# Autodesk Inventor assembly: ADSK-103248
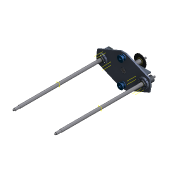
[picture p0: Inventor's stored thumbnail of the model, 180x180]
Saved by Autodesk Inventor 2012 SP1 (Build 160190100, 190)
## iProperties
Shininess: 0.0
Created: 2000-12
Part Number: ADSK-103248
Document SubType Name: Assembly
Designer: gao
Stock Number: ADSK-103248
Density: 0.0
Volumn: 0.0
Area: 0.0
PropertySet Name: Model Information
Control State: 0
Master: False
Checked Out: False
Author: gao
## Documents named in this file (15)
- D:\AOTC\Autodesk Inventor 2012 Essential for New Users\Autodesk Inventor 2012 Essentials - Project Files\Learning\Workspace\Sub-Assemblies\ADSK-103248.iam
- D:\AOTC\Autodesk Inventor 2012 Essential for New Users\Autodesk Inventor 2012 Essentials - Project Files\Learning\Workspace\Parts\ADSK-104071.ipt
- D:\AOTC\Autodesk Inventor 2012 Essential for New Users\Autodesk Inventor 2012 Essentials - Project Files\Learning\Workspace\Libraries\Content Center Files\en-US\4746AD94-7A15-4D0E-79EA-365386ECB28E.ipt
- D:\AOTC\Autodesk Inventor 2012 Essential for New Users\Autodesk Inventor 2012 Essentials - Project Files\Learning\Workspace\Sub-Assemblies\ADSK-103235.iam
- D:\AOTC\Autodesk Inventor 2012 Essential for New Users\Autodesk Inventor 2012 Essentials - Project Files\Learning\Workspace\Parts\ADSK-103456.ipt
- D:\AOTC\Autodesk Inventor 2012 Essential for New Users\Autodesk Inventor 2012 Essentials - Project Files\Learning\Workspace\Parts\ADSK-103406.ipt
- D:\AOTC\Autodesk Inventor 2012 Essential for New Users\Autodesk Inventor 2012 Essentials - Project Files\Learning\Workspace\Sub-Assemblies\ADSK-103223.iam
- D:\AOTC\Autodesk Inventor 2012 Essential for New Users\Autodesk Inventor 2012 Essentials - Project Files\Learning\Workspace\Parts\ADSK-103915.ipt
- D:\AOTC\Autodesk Inventor 2012 Essential for New Users\Autodesk Inventor 2012 Essentials - Project Files\Learning\Workspace\Parts\ADSK-103391.ipt
- D:\AOTC\Autodesk Inventor 2012 Essential for New Users\Autodesk Inventor 2012 Essentials - Project Files\Learning\Workspace\Parts\ADSK-104022.ipt
- D:\AOTC\Autodesk Inventor 2012 Essential for New Users\Autodesk Inventor 2012 Essentials - Project Files\Learning\Workspace\Parts\ADSK-103457.ipt
- D:\AOTC\Autodesk Inventor 2012 Essential for New Users\Autodesk Inventor 2012 Essentials - Project Files\Learning\Workspace\Parts\45665CD9-1C60-DBCA-D3BB-54EB80893890.ipt
- D:\AOTC\Autodesk Inventor 2012 Essential for New Users\Autodesk Inventor 2012 Essentials - Project Files\Learning\Workspace\Parts\F3808AAD-BDC4-3728-F238-65C25E68102C.ipt
- D:\AOTC\Autodesk Inventor 2012 Essential for New Users\Autodesk Inventor 2012 Essentials - Project Files\Learning\Workspace\Parts\707ED299-F0A9-17CF-8432-1254634F0CCD.ipt
- D:\AOTC\Autodesk Inventor 2012 Essential for New Users\Autodesk Inventor 2012 Essentials - Project Files\Learning\Workspace\Parts\018621A2-7339-DADC-0A62-9899783EECD1.ipt
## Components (56 placed, 14 different names)
1. ADSK-104071:1 — Insert:1, Insert:2, Insert:11, Mate:1, Insert:12, Mate:2, Insert:13, Insert:14, Insert:15, Angle:3, Angle:4, Insert:24, Insert:25, Insert:26, Insert:27, Insert:28, Insert:29, Insert:30, Insert:31
2. ADSK-103235:1 [sub-assembly] — Insert:4, Angle:1, Insert:13
3. ADSK-103235:2 [sub-assembly] — Insert:1, Insert:3, Angle:2
4. ADSK-103457:2 — Insert:15, Angle:4, Insert:20, Insert:21, Insert:22, Insert:23
5. ADSK-103457:1 — Insert:14, Angle:3, Insert:16, Insert:17, Insert:18, Insert:19
6. ADSK-103456:1 — Insert:2, Insert:5, Insert:8, Insert:9
7. ADSK-103406:1 — Insert:3, Insert:7
8. ADSK-103406:2 — Insert:4, Insert:6
9. ADSK-103223:1 [sub-assembly] — Insert:5
10. ADSK-103915:1 — Insert:6
11. ADSK-103915:2 — Insert:7
12. ADSK-103391:1 — Insert:8
13. ADSK-103391:2 — Insert:9, Insert:10
14. ADSK-103915:3 — Insert:10
15. ADSK-104022:1 — Insert:12, Mate:2, Angle:2, Insert:32, Insert:33, Insert:34, Insert:35
16. ADSK-104022:2 — Insert:11, Mate:1, Angle:1, Insert:36, Insert:37, Insert:38, Insert:39
17. Hex Cap Screw - 3/8 - 16 - 1 1/2:1
18. Hex Cap Screw - 3/8 - 16 - 1 1/2:2
19. Hex Cap Screw - 3/8 - 16 - 1 1/2:3 — Insert:21
20. Hex Cap Screw - 3/8 - 16 - 1 1/2:4
21. Hex Cap Screw - 3/8 - 16 - 1 1/2:5
22. Hex Cap Screw - 3/8 - 16 - 1 1/2:6
23. Hex Cap Screw - 3/8 - 16 - 1 1/2:7
24. Hex Cap Screw - 3/8 - 16 - 1 1/2:8
25. Helical Spring Lock Washer - 3/8  Regular. Carbon Steel:1 — Insert:23
26. Helical Spring Lock Washer - 3/8  Regular. Carbon Steel:2 — Insert:22
27. Helical Spring Lock Washer - 3/8  Regular. Carbon Steel:3
28. Helical Spring Lock Washer - 3/8  Regular. Carbon Steel:4 — Insert:20
29. Helical Spring Lock Washer - 3/8  Regular. Carbon Steel:5 — Insert:19
30. Helical Spring Lock Washer - 3/8  Regular. Carbon Steel:6 — Insert:18
31. Helical Spring Lock Washer - 3/8  Regular. Carbon Steel:7 — Insert:17
32. Helical Spring Lock Washer - 3/8  Regular. Carbon Steel:8 — Insert:16
33. Hexagon Socket Head Cap Screw - 3/8 - 16 - 1 1/2:1 — Insert:26
34. Hexagon Socket Head Cap Screw - 3/8 - 16 - 1 1/2:2 — Insert:27
35. Hexagon Socket Head Cap Screw - 3/8 - 16 - 1 1/2:3 — Insert:28
36. Hexagon Socket Head Cap Screw - 3/8 - 16 - 1 1/2:4 — Insert:29
37. Hexagon Socket Head Cap Screw - 3/8 - 16 - 1 1/2:5 — Insert:30
38. Hexagon Socket Head Cap Screw - 3/8 - 16 - 1 1/2:6 — Insert:25
39. Hexagon Socket Head Cap Screw - 3/8 - 16 - 1 1/2:7 — Insert:24
40. Hexagon Socket Head Cap Screw - 3/8 - 16 - 1 1/2:8 — Insert:31
41. Hex Cap Screw - 1/2 - 13 - 1 3/4:1
42. Hex Cap Screw - 1/2 - 13 - 1 3/4:2
43. Hex Cap Screw - 1/2 - 13 - 1 3/4:3
44. Hex Cap Screw - 1/2 - 13 - 1 3/4:4
45. Hex Cap Screw - 1/2 - 13 - 1 3/4:5
46. Hex Cap Screw - 1/2 - 13 - 1 3/4:6
47. Hex Cap Screw - 1/2 - 13 - 1 3/4:7
48. Hex Cap Screw - 1/2 - 13 - 1 3/4:8
49. Helical Spring Lock Washer - 1/2 Regular. Carbon Steel:1 — Insert:32
50. Helical Spring Lock Washer - 1/2 Regular. Carbon Steel:2 — Insert:33
51. Helical Spring Lock Washer - 1/2 Regular. Carbon Steel:3 — Insert:34
52. Helical Spring Lock Washer - 1/2 Regular. Carbon Steel:4 — Insert:35
53. Helical Spring Lock Washer - 1/2 Regular. Carbon Steel:5 — Insert:36
54. Helical Spring Lock Washer - 1/2 Regular. Carbon Steel:6 — Insert:37
55. Helical Spring Lock Washer - 1/2 Regular. Carbon Steel:7 — Insert:38
56. Helical Spring Lock Washer - 1/2 Regular. Carbon Steel:8 — Insert:39
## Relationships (45: Insert 39, Angle 4, Mate 2)
- Insert:1: ADSK-104071:1 ↔ ADSK-103235:2
- Insert:2: ADSK-104071:1 ↔ ADSK-103456:1
- Insert:3: ADSK-103235:2 ↔ ADSK-103406:1
- Insert:4: ADSK-103235:1 ↔ ADSK-103406:2
- Insert:5: ADSK-103456:1 ↔ ADSK-103223:1
- Insert:6: ADSK-103406:2 ↔ ADSK-103915:1
- Insert:7: ADSK-103406:1 ↔ ADSK-103915:2
- Insert:8: ADSK-103456:1 ↔ ADSK-103391:1
- Insert:9: ADSK-103456:1 ↔ ADSK-103391:2
- Insert:10: ADSK-103391:2 ↔ ADSK-103915:3
- Insert:11: ADSK-104071:1 ↔ ADSK-104022:2
- Mate:1: ADSK-104071:1 ↔ ADSK-104022:2
- Angle:1: ADSK-103235:1 ↔ ADSK-104022:2
- Insert:12: ADSK-104071:1 ↔ ADSK-104022:1
- Mate:2: ADSK-104071:1 ↔ ADSK-104022:1
- Angle:2: ADSK-103235:2 ↔ ADSK-104022:1
- Insert:13: ADSK-104071:1 ↔ ADSK-103235:1
- Insert:14: ADSK-104071:1 ↔ ADSK-103457:1
- Insert:15: ADSK-104071:1 ↔ ADSK-103457:2
- Angle:3: ADSK-104071:1 ↔ ADSK-103457:1
- Angle:4: ADSK-104071:1 ↔ ADSK-103457:2
- Insert:16: ADSK-103457:1 ↔ Helical Spring Lock Washer - 3/8  Regular. Carbon Steel:8
- Insert:17: ADSK-103457:1 ↔ Helical Spring Lock Washer - 3/8  Regular. Carbon Steel:7
- Insert:18: ADSK-103457:1 ↔ Helical Spring Lock Washer - 3/8  Regular. Carbon Steel:6
- Insert:19: ADSK-103457:1 ↔ Helical Spring Lock Washer - 3/8  Regular. Carbon Steel:5
- Insert:20: ADSK-103457:2 ↔ Helical Spring Lock Washer - 3/8  Regular. Carbon Steel:4
- Insert:21: ADSK-103457:2 ↔ Hex Cap Screw - 3/8 - 16 - 1 1/2:3
- Insert:22: ADSK-103457:2 ↔ Helical Spring Lock Washer - 3/8  Regular. Carbon Steel:2
- Insert:23: ADSK-103457:2 ↔ Helical Spring Lock Washer - 3/8  Regular. Carbon Steel:1
- Insert:24: ADSK-104071:1 ↔ Hexagon Socket Head Cap Screw - 3/8 - 16 - 1 1/2:7
- Insert:25: ADSK-104071:1 ↔ Hexagon Socket Head Cap Screw - 3/8 - 16 - 1 1/2:6
- Insert:26: ADSK-104071:1 ↔ Hexagon Socket Head Cap Screw - 3/8 - 16 - 1 1/2:1
- Insert:27: ADSK-104071:1 ↔ Hexagon Socket Head Cap Screw - 3/8 - 16 - 1 1/2:2
- Insert:28: ADSK-104071:1 ↔ Hexagon Socket Head Cap Screw - 3/8 - 16 - 1 1/2:3
- Insert:29: ADSK-104071:1 ↔ Hexagon Socket Head Cap Screw - 3/8 - 16 - 1 1/2:4
- Insert:30: ADSK-104071:1 ↔ Hexagon Socket Head Cap Screw - 3/8 - 16 - 1 1/2:5
- Insert:31: ADSK-104071:1 ↔ Hexagon Socket Head Cap Screw - 3/8 - 16 - 1 1/2:8
- Insert:32: ADSK-104022:1 ↔ Helical Spring Lock Washer - 1/2 Regular. Carbon Steel:1
- Insert:33: ADSK-104022:1 ↔ Helical Spring Lock Washer - 1/2 Regular. Carbon Steel:2
- Insert:34: ADSK-104022:1 ↔ Helical Spring Lock Washer - 1/2 Regular. Carbon Steel:3
- Insert:35: ADSK-104022:1 ↔ Helical Spring Lock Washer - 1/2 Regular. Carbon Steel:4
- Insert:36: ADSK-104022:2 ↔ Helical Spring Lock Washer - 1/2 Regular. Carbon Steel:5
- Insert:37: ADSK-104022:2 ↔ Helical Spring Lock Washer - 1/2 Regular. Carbon Steel:6
- Insert:38: ADSK-104022:2 ↔ Helical Spring Lock Washer - 1/2 Regular. Carbon Steel:7
- Insert:39: ADSK-104022:2 ↔ Helical Spring Lock Washer - 1/2 Regular. Carbon Steel:8
